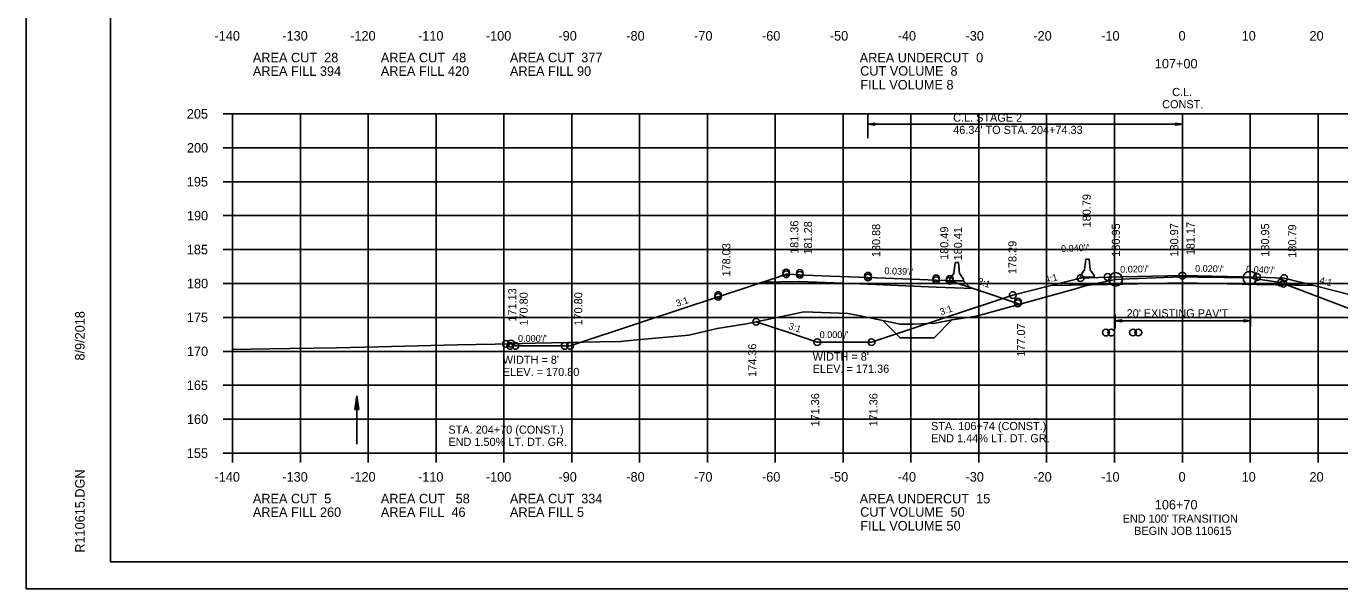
# Model space of a CAD drawing. Extents: x 1372132 to 1372465, y 380083 to 381790.
# Drawn here: x 1372131.6 to 1372325.2, y 380723.5 to 380806.4 of the extents above; entities that cross this region are included whole.
import ezdxf

# ---------------------------------------------------------------- set-up
doc = ezdxf.new("R2010")
doc.units = 0
for name, color, linetype in [('R_Alt Surface', 7, 'Continuous'), ('R_Axis', 7, 'Continuous'), ('R_Axis Annot', 7, 'Continuous'), ('R_Border', 7, 'Continuous'), ('R_Dimension', 7, 'Continuous'), ('R_Draft', 7, 'Continuous'), ('R_Erosion', 7, 'Continuous'), ('R_Exist Surface', 7, 'Continuous'), ('R_Fin Surface', 7, 'Continuous'), ('R_Grid', 7, 'Continuous'), ('R_No Plot', 7, 'Continuous'), ('R_Xsect Elev', 7, 'Continuous'), ('R_Xsect Slope', 7, 'Continuous')]:
    doc.layers.add(name, color=color, linetype=linetype)

msp = doc.modelspace()

# ---------------------------------------------------------------- linework, layer by layer
at = {"layer": 'R_Alt Surface'}
for points in [[(1372271.13, 380767.76), (1372265.72, 380767.97), (1372255.67, 380768.37), (1372245.63, 380768.76), (1372240.04, 380768.66)], [(1372321.38, 380768.19), (1372313.01, 380768.36), (1372302.01, 380768.58), (1372291.01, 380768.36), (1372282.65, 380768.19)]]:
    msp.add_lwpolyline(points, dxfattribs=at)
at = {"layer": 'R_Axis'}
for p, q in [((1372160.61, 380793.49), (1372162.01, 380793.49)), ((1372162.01, 380743.49), (1372162.01, 380793.49)), ((1372160.61, 380788.49), (1372162.01, 380788.49)), ((1372160.61, 380783.49), (1372162.01, 380783.49)), ((1372160.61, 380778.49), (1372162.01, 380778.49)), ((1372160.61, 380773.49), (1372162.01, 380773.49)), ((1372160.61, 380768.49), (1372162.01, 380768.49)), ((1372160.61, 380763.49), (1372162.01, 380763.49)), ((1372160.61, 380758.49), (1372162.01, 380758.49)), ((1372160.61, 380753.49), (1372162.01, 380753.49)), ((1372160.61, 380748.49), (1372162.01, 380748.49)), ((1372160.61, 380743.49), (1372162.01, 380743.49)), ((1372162.01, 380743.49), (1372442.01, 380743.49)), ((1372162.01, 380742.09), (1372162.01, 380743.49)), ((1372172.01, 380742.09), (1372172.01, 380743.49)), ((1372182.01, 380742.09), (1372182.01, 380743.49)), ((1372192.01, 380742.09), (1372192.01, 380743.49)), ((1372202.01, 380742.09), (1372202.01, 380743.49)), ((1372212.01, 380742.09), (1372212.01, 380743.49)), ((1372222.01, 380742.09), (1372222.01, 380743.49)), ((1372232.01, 380742.09), (1372232.01, 380743.49)), ((1372242.01, 380742.09), (1372242.01, 380743.49)), ((1372252.01, 380742.09), (1372252.01, 380743.49)), ((1372262.01, 380742.09), (1372262.01, 380743.49)), ((1372272.01, 380742.09), (1372272.01, 380743.49)), ((1372282.01, 380742.09), (1372282.01, 380743.49)), ((1372292.01, 380742.09), (1372292.01, 380743.49)), ((1372302.01, 380742.09), (1372302.01, 380743.49)), ((1372312.01, 380742.09), (1372312.01, 380743.49)), ((1372322.01, 380742.09), (1372322.01, 380743.49))]:
    msp.add_line(p, q, dxfattribs=at)
at = {"layer": 'R_Border'}
for p, q in [((1372144.01, 380727.49), (1372144.01, 380932.95)), ((1372144.01, 380727.49), (1372144.01, 380727.49)), ((1372460.19, 380727.49), (1372144.01, 380727.49))]:
    msp.add_line(p, q, dxfattribs=at)
at = {"layer": 'R_Dimension'}
for p, q in [((1372180.02, 380749.93), (1372180.32, 380751.93)), ((1372180.02, 380749.93), (1372180.32, 380751.93)), ((1372180.62, 380749.93), (1372180.32, 380751.93)), ((1372180.62, 380749.93), (1372180.32, 380751.93)), ((1372180.07, 380749.93), (1372180.32, 380751.6)), ((1372180.07, 380749.93), (1372180.32, 380751.6)), ((1372180.12, 380749.93), (1372180.32, 380751.25)), ((1372180.12, 380749.93), (1372180.32, 380751.25)), ((1372180.17, 380749.93), (1372180.32, 380750.92)), ((1372180.17, 380749.93), (1372180.32, 380750.92)), ((1372180.23, 380749.93), (1372180.32, 380750.58)), ((1372180.23, 380749.93), (1372180.32, 380750.58)), ((1372180.28, 380749.93), (1372180.32, 380750.25)), ((1372180.28, 380749.93), (1372180.32, 380750.25)), ((1372180.57, 380749.93), (1372180.32, 380751.6)), ((1372180.57, 380749.93), (1372180.32, 380751.6)), ((1372180.52, 380749.93), (1372180.32, 380751.25)), ((1372180.52, 380749.93), (1372180.32, 380751.25)), ((1372180.47, 380749.93), (1372180.32, 380750.92)), ((1372180.47, 380749.93), (1372180.32, 380750.92)), ((1372180.42, 380749.93), (1372180.32, 380750.58)), ((1372180.42, 380749.93), (1372180.32, 380750.58)), ((1372180.37, 380749.93), (1372180.32, 380750.25)), ((1372180.37, 380749.93), (1372180.32, 380750.25)), ((1372180.02, 380749.93), (1372180.62, 380749.93)), ((1372180.02, 380749.93), (1372180.62, 380749.93))]:
    msp.add_line(p, q, dxfattribs=at)
at = {"layer": 'R_Draft'}
for p, q in [((1372255.67, 380789.89), (1372255.67, 380793.49)), ((1372302.01, 380793.49), (1372302.01, 380789.89)), ((1372256.67, 380792.13), (1372255.67, 380791.98)), ((1372256.67, 380792.13), (1372255.67, 380791.98)), ((1372255.67, 380791.98), (1372302.01, 380791.98)), ((1372256.67, 380791.83), (1372255.67, 380791.98)), ((1372256.67, 380791.83), (1372255.67, 380791.98)), ((1372256.67, 380792.1), (1372255.84, 380791.98)), ((1372256.67, 380792.1), (1372255.84, 380791.98)), ((1372256.67, 380791.85), (1372255.84, 380791.98)), ((1372256.67, 380791.85), (1372255.84, 380791.98)), ((1372256.67, 380792.08), (1372256.01, 380791.98)), ((1372256.67, 380792.08), (1372256.01, 380791.98)), ((1372256.67, 380791.88), (1372256.01, 380791.98)), ((1372256.67, 380791.88), (1372256.01, 380791.98)), ((1372256.67, 380792.05), (1372256.18, 380791.98)), ((1372256.67, 380792.05), (1372256.18, 380791.98)), ((1372256.67, 380791.9), (1372256.18, 380791.98)), ((1372256.67, 380791.9), (1372256.18, 380791.98)), ((1372256.67, 380792.02), (1372256.35, 380791.98)), ((1372256.67, 380792.02), (1372256.35, 380791.98)), ((1372256.67, 380791.93), (1372256.35, 380791.98)), ((1372256.67, 380791.93), (1372256.35, 380791.98)), ((1372256.67, 380792), (1372256.51, 380791.98)), ((1372256.67, 380792), (1372256.51, 380791.98)), ((1372256.67, 380791.95), (1372256.51, 380791.98)), ((1372256.67, 380791.95), (1372256.51, 380791.98)), ((1372256.67, 380791.83), (1372256.67, 380792.13)), ((1372256.67, 380791.83), (1372256.67, 380792.13)), ((1372301.01, 380792.13), (1372302.01, 380791.98)), ((1372301.01, 380792.13), (1372301.01, 380791.83)), ((1372301.01, 380792.13), (1372302.01, 380791.98)), ((1372301.01, 380792.13), (1372301.01, 380791.83)), ((1372301.01, 380792.1), (1372301.85, 380791.98)), ((1372301.01, 380792.1), (1372301.85, 380791.98)), ((1372301.01, 380792.08), (1372301.68, 380791.98)), ((1372301.01, 380792.08), (1372301.68, 380791.98)), ((1372301.01, 380792.05), (1372301.51, 380791.98)), ((1372301.01, 380792.05), (1372301.51, 380791.98)), ((1372301.01, 380792.02), (1372301.34, 380791.98)), ((1372301.01, 380792.02), (1372301.34, 380791.98)), ((1372301.01, 380792), (1372301.17, 380791.98)), ((1372301.01, 380792), (1372301.17, 380791.98)), ((1372301.01, 380791.83), (1372302.01, 380791.98)), ((1372301.01, 380791.93), (1372301.34, 380791.98)), ((1372301.01, 380791.88), (1372301.68, 380791.98)), ((1372301.01, 380791.85), (1372301.85, 380791.98)), ((1372301.01, 380791.9), (1372301.51, 380791.98)), ((1372301.01, 380791.95), (1372301.17, 380791.98)), ((1372301.01, 380791.83), (1372302.01, 380791.98)), ((1372301.01, 380791.93), (1372301.34, 380791.98)), ((1372301.01, 380791.88), (1372301.68, 380791.98)), ((1372301.01, 380791.85), (1372301.85, 380791.98)), ((1372301.01, 380791.9), (1372301.51, 380791.98)), ((1372301.01, 380791.95), (1372301.17, 380791.98)), ((1372268.51, 380771.56), (1372268.33, 380769.98)), ((1372268.51, 380771.56), (1372269.01, 380771.56)), ((1372269.18, 380769.98), (1372269.01, 380771.56)), ((1372287.76, 380772.09), (1372287.59, 380770.51)), ((1372287.76, 380772.09), (1372288.26, 380772.09)), ((1372288.44, 380770.51), (1372288.26, 380772.09)), ((1372268.33, 380769.98), (1372267.76, 380769.14)), ((1372269.76, 380769.14), (1372269.18, 380769.98)), ((1372287.59, 380770.51), (1372287.01, 380769.68)), ((1372287.01, 380769.43), (1372287.01, 380769.68)), ((1372287.01, 380769.43), (1372289.01, 380769.43)), ((1372289.01, 380769.68), (1372288.44, 380770.51)), ((1372289.01, 380769.43), (1372289.01, 380769.68)), ((1372267.76, 380768.89), (1372267.76, 380769.14)), ((1372267.76, 380768.89), (1372269.76, 380768.89)), ((1372269.76, 380768.89), (1372269.76, 380769.14)), ((1372292.09, 380763.9), (1372292.09, 380761.89)), ((1372312.07, 380763.9), (1372312.07, 380762.13)), ((1372293.09, 380763.13), (1372292.09, 380762.98)), ((1372293.09, 380763.13), (1372292.09, 380762.98)), ((1372312.07, 380762.98), (1372292.09, 380762.98)), ((1372293.09, 380762.83), (1372292.09, 380762.98)), ((1372293.09, 380762.83), (1372292.09, 380762.98)), ((1372292.09, 380762.13), (1372292.09, 380762.13)), ((1372293.09, 380763.11), (1372292.26, 380762.98)), ((1372293.09, 380763.11), (1372292.26, 380762.98)), ((1372293.09, 380762.86), (1372292.26, 380762.98)), ((1372293.09, 380762.86), (1372292.26, 380762.98)), ((1372293.09, 380763.08), (1372292.43, 380762.98)), ((1372293.09, 380763.08), (1372292.43, 380762.98)), ((1372293.09, 380762.88), (1372292.43, 380762.98)), ((1372293.09, 380762.88), (1372292.43, 380762.98)), ((1372293.09, 380763.06), (1372292.6, 380762.98)), ((1372293.09, 380763.06), (1372292.6, 380762.98)), ((1372293.09, 380762.91), (1372292.6, 380762.98)), ((1372293.09, 380762.91), (1372292.6, 380762.98)), ((1372293.09, 380763.03), (1372292.77, 380762.98)), ((1372293.09, 380763.03), (1372292.77, 380762.98)), ((1372293.09, 380762.94), (1372292.77, 380762.98)), ((1372293.09, 380762.94), (1372292.77, 380762.98)), ((1372293.09, 380763.01), (1372292.93, 380762.98)), ((1372293.09, 380763.01), (1372292.93, 380762.98)), ((1372293.09, 380762.96), (1372292.93, 380762.98)), ((1372293.09, 380762.96), (1372292.93, 380762.98)), ((1372293.09, 380762.83), (1372293.09, 380763.13)), ((1372293.09, 380762.83), (1372293.09, 380763.13)), ((1372311.07, 380763.13), (1372312.07, 380762.98)), ((1372311.07, 380763.13), (1372311.07, 380762.83)), ((1372311.07, 380763.11), (1372311.9, 380762.98)), ((1372311.07, 380763.08), (1372311.73, 380762.98)), ((1372311.07, 380763.06), (1372311.57, 380762.98)), ((1372311.07, 380763.03), (1372311.4, 380762.98)), ((1372311.07, 380763.01), (1372311.23, 380762.98)), ((1372311.07, 380762.83), (1372312.07, 380762.98)), ((1372311.07, 380762.93), (1372311.4, 380762.98)), ((1372311.07, 380762.88), (1372311.73, 380762.98)), ((1372311.07, 380762.86), (1372311.9, 380762.98)), ((1372311.07, 380762.91), (1372311.57, 380762.98)), ((1372311.07, 380762.96), (1372311.23, 380762.98)), ((1372180.32, 380744.79), (1372180.32, 380751.93))]:
    msp.add_line(p, q, dxfattribs=at)
at = {"layer": 'R_Erosion'}
for p, q in [((1372269.82, 380768.81), (1372267.1, 380768.92)), ((1372269.82, 380768.81), (1372270.73, 380767.9)), ((1372260.4, 380760.5), (1372257.91, 380762.99)), ((1372265.41, 380760.5), (1372268.04, 380763.14)), ((1372260.4, 380760.5), (1372265.41, 380760.5))]:
    msp.add_line(p, q, dxfattribs=at)
at = {"layer": 'R_Exist Surface'}
msp.add_lwpolyline([(1372162.01, 380758.77), (1372167.53, 380758.86), (1372170.44, 380758.9), (1372177.33, 380759.02), (1372183.51, 380759.17), (1372185.44, 380759.21), (1372195.11, 380759.44), (1372200.74, 380759.56), (1372206.67, 380759.7), (1372216.09, 380759.89), (1372219.18, 380759.96), (1372221.65, 380760.18), (1372229.25, 380760.88), (1372233.46, 380761.88), (1372237.76, 380762.55), (1372246.28, 380764.29), (1372252.69, 380764.09), (1372254.76, 380763.65), (1372260.41, 380762.5), (1372262.45, 380762.5), (1372265.56, 380762.64), (1372268.07, 380763.15), (1372271.66, 380763.69), (1372286.28, 380767.71), (1372287.7, 380768.12), (1372288.86, 380768.37), (1372292.18, 380769.1), (1372294.23, 380769.17), (1372301.9, 380769.46), (1372304.32, 380769.42), (1372311.96, 380769.3), (1372312.85, 380769.18), (1372316.46, 380768.64), (1372326.44, 380764.85)], dxfattribs=at)
at = {"layer": 'R_Fin Surface'}
for points in [[(1372203.05, 380759.62), (1372203.28, 380759.51), (1372203.72, 380759.29), (1372209.21, 380759.29), (1372211.77, 380759.29), (1372222.3, 380762.78), (1372233.59, 380766.52), (1372242.26, 380769.39), (1372243.62, 380769.85), (1372243.85, 380769.84), (1372245.63, 380769.76), (1372246.32, 380769.74), (1372250.15, 380769.58), (1372255.67, 380769.37), (1372263.34, 380769.06), (1372265.72, 380768.97), (1372267.1, 380768.92), (1372267.73, 380768.9), (1372271.78, 380767.55), (1372277.77, 380765.56), (1372278.09, 380765.45)], [(1372239.2, 380762.85), (1372244.03, 380761.25), (1372248.2, 380759.84), (1372256.2, 380759.84), (1372266.67, 380763.32), (1372277.01, 380766.78), (1372282.65, 380768.19), (1372287.01, 380769.28), (1372291.01, 380769.44), (1372302.01, 380769.66), (1372313.01, 380769.44), (1372317.01, 380769.28), (1372321.38, 380768.19), (1372327.01, 380766.78), (1372335.18, 380764.05), (1372343.51, 380761.28), (1372347.51, 380761.28), (1372352.36, 380762.91), (1372357.35, 380764.56)]]:
    msp.add_lwpolyline(points, dxfattribs=at)
at = {"layer": 'R_Grid'}
for p, q in [((1372162.01, 380793.49), (1372442.01, 380793.49)), ((1372162.01, 380743.49), (1372162.01, 380793.49)), ((1372172.01, 380743.49), (1372172.01, 380793.49)), ((1372182.01, 380743.49), (1372182.01, 380793.49)), ((1372192.01, 380743.49), (1372192.01, 380793.49)), ((1372202.01, 380743.49), (1372202.01, 380793.49)), ((1372212.01, 380743.49), (1372212.01, 380793.49)), ((1372222.01, 380743.49), (1372222.01, 380793.49)), ((1372232.01, 380743.49), (1372232.01, 380793.49)), ((1372242.01, 380743.49), (1372242.01, 380793.49)), ((1372252.01, 380743.49), (1372252.01, 380793.49)), ((1372262.01, 380743.49), (1372262.01, 380793.49)), ((1372272.01, 380743.49), (1372272.01, 380793.49)), ((1372282.01, 380743.49), (1372282.01, 380793.49)), ((1372292.01, 380743.49), (1372292.01, 380793.49)), ((1372302.01, 380743.49), (1372302.01, 380793.49)), ((1372312.01, 380743.49), (1372312.01, 380793.49)), ((1372322.01, 380743.49), (1372322.01, 380793.49)), ((1372162.01, 380788.49), (1372442.01, 380788.49)), ((1372162.01, 380783.49), (1372442.01, 380783.49)), ((1372162.01, 380778.49), (1372442.01, 380778.49)), ((1372162.01, 380773.49), (1372442.01, 380773.49)), ((1372162.01, 380768.49), (1372442.01, 380768.49)), ((1372162.01, 380763.49), (1372442.01, 380763.49)), ((1372162.01, 380758.49), (1372442.01, 380758.49)), ((1372162.01, 380753.49), (1372442.01, 380753.49)), ((1372162.01, 380748.49), (1372442.01, 380748.49)), ((1372162.01, 380743.49), (1372442.01, 380743.49))]:
    msp.add_line(p, q, dxfattribs=at)
at = {"layer": 'R_No Plot'}
msp.add_line((1372131.61, 380723.51), (1372464.95, 380723.51), dxfattribs=at)
for points in [[(1372131.61, 380936.84), (1372464.95, 380936.84), (1372464.95, 380723.5), (1372131.61, 380723.5)], [(1372377.93, 380932.95), (1372377.93, 380923.07), (1372413.67, 380923.07), (1372413.67, 380920.15), (1372436.87, 380920.15), (1372436.87, 380895.81), (1372460.19, 380895.81), (1372460.19, 380727.49), (1372144.01, 380727.49), (1372144.01, 380932.95)], [(1372288.56, 380768.31), (1372288.86, 380768.37), (1372292.18, 380769.1), (1372294.23, 380769.17), (1372301.9, 380769.46), (1372304.32, 380769.42), (1372311.96, 380769.3), (1372312.85, 380769.18), (1372316.46, 380768.64), (1372317.43, 380768.27), (1372313.01, 380768.36), (1372302.01, 380768.58), (1372291.01, 380768.36)], [(1372264.47, 380762.59), (1372265.56, 380762.64), (1372268.07, 380763.15), (1372271.66, 380763.69), (1372286.28, 380767.71), (1372287.7, 380768.12), (1372288.56, 380768.31), (1372282.65, 380768.19), (1372277.01, 380766.78), (1372266.67, 380763.32)], [(1372317.43, 380768.27), (1372326.44, 380764.85), (1372329.31, 380763.76), (1372330.26, 380763.44), (1372333.41, 380761.92), (1372335.9, 380763.07), (1372336.73, 380763.38), (1372337.09, 380763.41), (1372335.18, 380764.05), (1372327.01, 380766.78), (1372321.38, 380768.19)], [(1372239.2, 380762.85), (1372246.28, 380764.29), (1372252.69, 380764.09), (1372254.76, 380763.65), (1372260.41, 380762.5), (1372262.45, 380762.5), (1372264.47, 380762.59), (1372256.2, 380759.84), (1372248.2, 380759.84), (1372244.03, 380761.25)]]:
    msp.add_lwpolyline(points, close=True, dxfattribs=at)
for centre, radius in [((1372243.62, 380770.11), 0.5), ((1372243.62, 380769.85), 0.5), ((1372245.63, 380770.03), 0.5), ((1372245.63, 380769.76), 0.5), ((1372255.67, 380769.63), 0.5), ((1372255.67, 380769.37), 0.5), ((1372265.72, 380769.24), 0.5), ((1372265.72, 380768.97), 0.5), ((1372267.73, 380769.16), 0.5), ((1372267.73, 380768.9), 0.5), ((1372287.01, 380769.28), 0.5), ((1372291.01, 380769.44), 0.5), ((1372292.18, 380769.1), 1), ((1372302.01, 380769.66), 0.5), ((1372311.96, 380769.3), 1), ((1372313.01, 380769.44), 0.5), ((1372317.01, 380769.28), 0.5), ((1372316.54, 380768.61), 0.5), ((1372316.91, 380768.47), 0.5), ((1372233.59, 380766.78), 0.5), ((1372233.59, 380766.52), 0.5), ((1372277.01, 380766.78), 0.5), ((1372277.77, 380765.82), 0.5), ((1372277.77, 380765.56), 0.5), ((1372239.2, 380762.85), 0.5), ((1372290.75, 380761.26), 0.5), ((1372291.53, 380761.26), 0.5), ((1372294.74, 380761.27), 0.5), ((1372295.52, 380761.27), 0.5), ((1372202.3, 380759.6), 0.5), ((1372202.93, 380759.29), 0.5), ((1372203.05, 380759.62), 0.5), ((1372203.72, 380759.29), 0.5), ((1372210.97, 380759.29), 0.5), ((1372211.77, 380759.29), 0.5), ((1372248.2, 380759.84), 0.5), ((1372256.2, 380759.84), 0.5)]:
    msp.add_circle(centre, radius, dxfattribs=at)
at = {"layer": 'R_Xsect Elev'}
msp.add_line((1372302.01, 380769.46), (1372302.01, 380779.46), dxfattribs=at)

# ---------------------------------------------------------------- texts
at = {"layer": 'R_Axis Annot'}
for s, p in [('-140', (1372159.35, 380804.29)), ('-130', (1372169.35, 380804.29)), ('-120', (1372179.35, 380804.29)), ('-110', (1372189.35, 380804.29)), ('-100', (1372199.35, 380804.29)), ('-90', (1372210.05, 380804.29)), ('-80', (1372220.05, 380804.29)), ('-70', (1372230.05, 380804.29)), ('-60', (1372240.05, 380804.29)), ('-50', (1372250.05, 380804.29)), ('-40', (1372260.05, 380804.29)), ('-30', (1372270.05, 380804.29)), ('-20', (1372280.05, 380804.29)), ('-10', (1372290.05, 380804.29)), ('0', (1372301.45, 380804.29)), ('10', (1372310.75, 380804.29)), ('20', (1372320.75, 380804.29)), ('AREA CUT  28', (1372165.01, 380801.09)), ('AREA CUT  48', (1372183.87, 380801.09)), ('AREA CUT  377', (1372202.9, 380801.09)), ('AREA UNDERCUT  0', (1372254.45, 380801.08)), ('AREA FILL 394', (1372165.01, 380799.09)), ('AREA FILL 420', (1372183.87, 380799.09)), ('AREA FILL 90', (1372202.9, 380799.09)), ('CUT VOLUME  8', (1372254.52, 380799.12)), ('107+00', (1372297.95, 380800.19)), ('FILL VOLUME 8', (1372254.55, 380797.08)), ('205', (1372155.27, 380792.79)), ('200', (1372155.29, 380787.79)), ('195', (1372155.27, 380782.79)), ('190', (1372155.29, 380777.79)), ('185', (1372155.27, 380772.79)), ('180', (1372155.29, 380767.79)), ('175', (1372155.27, 380762.79)), ('170', (1372155.29, 380757.79)), ('165', (1372155.27, 380752.79)), ('160', (1372155.29, 380747.79)), ('155', (1372155.27, 380742.79)), ('-140', (1372159.35, 380739.29)), ('-130', (1372169.35, 380739.29)), ('-120', (1372179.35, 380739.29)), ('-110', (1372189.35, 380739.29)), ('-100', (1372199.35, 380739.29)), ('-90', (1372210.05, 380739.29)), ('-80', (1372220.05, 380739.29)), ('-70', (1372230.05, 380739.29)), ('-60', (1372240.05, 380739.29)), ('-50', (1372250.05, 380739.29)), ('-40', (1372260.05, 380739.29)), ('-30', (1372270.05, 380739.29)), ('-20', (1372280.05, 380739.29)), ('-10', (1372290.05, 380739.29)), ('0', (1372301.45, 380739.29)), ('10', (1372310.75, 380739.29)), ('20', (1372320.75, 380739.29)), ('AREA CUT  5', (1372165.01, 380736.09)), ('AREA CUT   58', (1372183.87, 380736.09)), ('AREA CUT  334', (1372202.9, 380736.09)), ('AREA UNDERCUT  15', (1372254.45, 380736.08)), ('106+70', (1372297.95, 380735.19)), ('AREA FILL 260', (1372165.01, 380734.09)), ('AREA FILL  46', (1372183.87, 380734.09)), ('AREA FILL 5', (1372202.9, 380734.09)), ('CUT VOLUME  50', (1372254.52, 380734.12)), ('FILL VOLUME 50', (1372254.55, 380732.08))]:
    msp.add_text(s, height=1.4, dxfattribs=at).set_placement(p)
at = {"layer": 'R_Border'}
for s, p in [('8/9/2018', (1372140.21, 380757.13)), ('R110615.DGN', (1372140.21, 380728.81))]:
    msp.add_text(s, height=1.4, rotation=90, dxfattribs=at).set_placement(p)
at = {"layer": 'R_Dimension'}
for s, p in [("WIDTH = 8'", (1372201.84, 380756.65)), ("WIDTH = 8'", (1372247.52, 380757.12)), ('ELEV. = 170.80', (1372201.84, 380754.85)), ('ELEV. = 171.36', (1372247.52, 380755.32))]:
    msp.add_text(s, height=1.2, dxfattribs=at).set_placement(p)
at = {"layer": 'R_Draft'}
for s, p in [('C.L. ', (1372300.51, 380796.11)), ('CONST. ', (1372299.04, 380794.31)), ('C.L. STAGE 2', (1372268.23, 380792.33)), ("46.34' TO STA. 204+74.33", (1372268.23, 380790.53)), ("20' EXISTING PAV'T", (1372293.8, 380763.5))]:
    msp.add_text(s, height=1.2, rotation=360, dxfattribs=at).set_placement(p)
for s, p in [('STA. 106+74 (CONST.)', (1372264.97, 380746.88)), ('STA. 204+70 (CONST.)', (1372193.83, 380746.35)), ('END 1.44% LT. DT. GR.', (1372264.97, 380745.08)), ('END 1.50% LT. DT. GR.', (1372193.83, 380744.55)), ("END 100' TRANSITION", (1372293.21, 380733.24)), ('BEGIN JOB 110615', (1372294.91, 380731.44))]:
    msp.add_text(s, height=1.2, dxfattribs=at).set_placement(p)
at = {"layer": 'R_Xsect Elev'}
for s, p in [('180.79', (1372288.5, 380776.76)), ('181.36', (1372245.42, 380772.85)), ('181.28', (1372247.43, 380772.76)), ('180.88', (1372257.47, 380772.37)), ('180.95', (1372292.81, 380772.44)), ('180.97', (1372301.41, 380772.46)), ('181.17', (1372303.81, 380772.66)), ('180.95', (1372314.81, 380772.44)), ('180.79', (1372318.81, 380772.28)), ('180.49', (1372267.52, 380771.97)), ('180.41', (1372269.53, 380771.9)), ('178.03', (1372235.39, 380769.52)), ('178.29', (1372277.56, 380769.87)), ('171.13', (1372203.84, 380762.87)), ('170.80', (1372205.52, 380762.29)), ('170.80', (1372213.57, 380762.29)), ('177.07', (1372278.84, 380757.69)), ('174.36', (1372239.22, 380754.72)), ('171.36', (1372248.48, 380747.41)), ('171.36', (1372257.07, 380747.41))]:
    msp.add_text(s, height=1.2, rotation=90, dxfattribs=at).set_placement(p)
at = {"layer": 'R_Xsect Slope'}
for s, rotation, p in [("0.040'/'", 2.2906, (1372284.15, 380773.12)), ("0.020'/'", 358.8542, (1372303.88, 380770.22)), ("0.039'/'", 357.7647, (1372258.08, 380769.87)), ('3:1', 341.6432, (1372271.75, 380768.41)), ('4:1', 14.0362, (1372281.89, 380768.52)), ("0.020'/'", 1.1458, (1372292.85, 380770.08)), ("0.040'/'", 357.7094, (1372311.39, 380770.11)), ('4:1', 345.9638, (1372322.14, 380768.52)), ('3:1', 18.3353, (1372227.54, 380765.04)), ('3:1', 18.4332, (1372266.45, 380763.79)), ('3:1', 341.5651, (1372243.86, 380761.82)), ("0.000'/'", 360, (1372204.09, 380759.89)), ("0.000'/'", 360, (1372248.55, 380760.44))]:
    msp.add_text(s, height=1, rotation=rotation, dxfattribs=at).set_placement(p)

doc.saveas('drawing.dxf')
